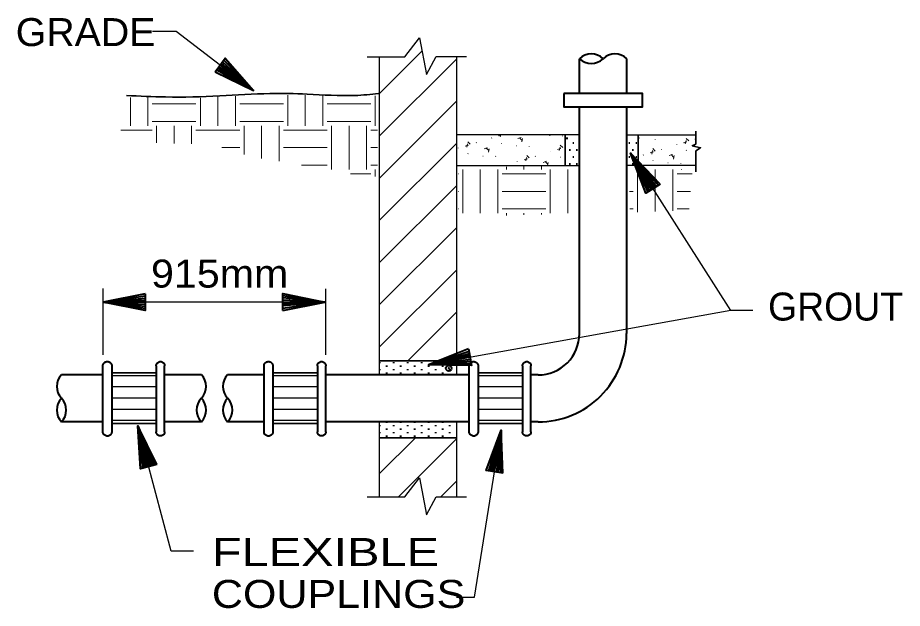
# Model space of a CAD drawing. Extents: x 55 to 190, y 198 to 264.
# Drawn here: x 79.2 to 87.22, y 208.06 to 213.42 of the extents above; entities that cross this region are included whole.
import ezdxf
from ezdxf.enums import TextEntityAlignment as Align

# ---------------------------------------------------------------- set-up
doc = ezdxf.new("R2010")
doc.units = 0
doc.header["$LTSCALE"] = 0.1
doc.header["$PDMODE"] = 32
doc.header["$PDSIZE"] = 0.05
doc.layers.add('2', color=7, linetype='Continuous', lineweight=40)

msp = doc.modelspace()

# ---------------------------------------------------------------- linework, layer by layer
at = {"layer": '2', "lineweight": 13}
for p, q in [((82.4802, 212.7318), (82.8647, 213.1162)), ((82.4805, 212.3487), (83.1772, 213.0456)), ((80.2186, 212.44), (80.2186, 212.6974)), ((80.3773, 212.44), (80.3773, 212.6974)), ((80.8536, 212.44), (80.8536, 212.6932)), ((81.0123, 212.44), (81.0123, 212.7014)), ((81.1711, 212.44), (81.1711, 212.7093)), ((81.6473, 212.44), (81.6473, 212.717)), ((81.8061, 212.44), (81.8061, 212.7175)), ((81.9648, 212.44), (81.9648, 212.7202)), ((82.4411, 212.44), (82.4411, 212.7106)), ((80.417, 212.6384), (80.8139, 212.6384)), ((81.2108, 212.6384), (81.6076, 212.6384)), ((82.0045, 212.6384), (82.4014, 212.6384)), ((82.4805, 211.9656), (83.1772, 212.6625)), ((80.417, 212.4797), (80.8139, 212.4797)), ((80.4567, 212.2844), (80.4567, 212.44)), ((80.6155, 212.2796), (80.6155, 212.44)), ((80.7742, 212.2746), (80.7742, 212.44)), ((81.2108, 212.4797), (81.6076, 212.4797)), ((81.2505, 212.1791), (81.2505, 212.44)), ((81.4092, 212.1418), (81.4092, 212.44)), ((81.568, 212.1201), (81.568, 212.44)), ((82.0045, 212.4797), (82.4014, 212.4797)), ((82.0442, 212.0431), (82.0442, 212.44)), ((82.203, 212.0431), (82.203, 212.44)), ((82.3617, 212.0431), (82.3617, 212.44)), ((80.1305, 212.4003), (80.417, 212.4003)), ((80.8139, 212.4003), (81.2108, 212.4003)), ((81.6076, 212.4003), (82.0045, 212.4003)), ((82.4014, 212.4003), (82.4617, 212.4003)), ((83.56, 212.3484), (83.5904, 212.3577)), ((83.5793, 212.3587), (83.5746, 212.3381)), ((82.4805, 211.5827), (83.1772, 212.2794)), ((83.2777, 212.2762), (83.2706, 212.2455)), ((83.3026, 212.2722), (83.2795, 212.2937)), ((83.3576, 212.2865), (83.3608, 212.2873)), ((83.497, 212.3288), (83.4976, 212.3315)), ((83.5865, 212.2796), (83.5841, 212.2788)), ((83.7637, 212.3339), (83.7333, 212.3246)), ((83.7494, 212.332), (83.7725, 212.3106)), ((83.7711, 212.2928), (83.7783, 212.3238)), ((84.0262, 212.3497), (84.0243, 212.3516)), ((84.1416, 212.3484), (84.141, 212.3458)), ((84.9816, 212.3175), (84.9811, 212.3148)), ((85.2391, 212.2862), (85.2695, 212.2955)), ((85.2618, 212.3071), (85.2547, 212.2762)), ((85.2859, 212.304), (85.2626, 212.3257)), ((85.3404, 212.3172), (85.3433, 212.318)), ((81.0478, 212.2415), (81.2108, 212.2415)), ((81.6076, 212.2415), (82.0045, 212.2415)), ((82.4014, 212.2415), (82.4617, 212.2415)), ((83.1933, 212.2362), (83.1938, 212.2386)), ((83.2565, 212.2555), (83.2867, 212.2648)), ((83.46, 212.241), (83.4296, 212.2317)), ((83.4457, 212.2392), (83.4687, 212.2175)), ((83.4674, 212.2), (83.4745, 212.2309)), ((83.7225, 212.2569), (83.7206, 212.2587)), ((83.8378, 212.2555), (83.8373, 212.2532)), ((84.0333, 212.205), (84.0339, 212.2077)), ((84.0961, 212.2243), (84.1262, 212.2336)), ((84.1177, 212.2452), (84.1106, 212.2143)), ((84.1424, 212.2415), (84.1191, 212.2632)), ((84.9356, 212.1934), (84.9657, 212.2026)), ((84.9578, 212.2143), (84.9507, 212.1833)), ((84.9821, 212.2108), (84.9589, 212.2325)), ((85.0366, 212.2243), (85.0398, 212.2251)), ((85.1771, 212.2669), (85.1777, 212.2693)), ((85.2655, 212.2175), (85.2631, 212.2167)), ((83.283, 212.1868), (83.2803, 212.186)), ((83.4187, 212.1637), (83.4169, 212.1656)), ((83.5341, 212.1629), (83.5335, 212.1603)), ((83.7293, 212.1124), (83.7301, 212.1148)), ((83.7923, 212.1315), (83.8227, 212.141)), ((83.814, 212.1526), (83.8069, 212.1217)), ((83.8386, 212.1487), (83.8153, 212.1701)), ((83.8934, 212.1624), (83.8966, 212.1635)), ((83.996, 212.1172), (83.9656, 212.1079)), ((83.9815, 212.1156), (84.0048, 212.0939)), ((84.1225, 212.1558), (84.1199, 212.155)), ((84.8734, 212.1741), (84.8739, 212.1767)), ((84.962, 212.1249), (84.9594, 212.1241)), ((85.139, 212.1788), (85.1086, 212.1696)), ((85.125, 212.178), (85.1483, 212.1563)), ((85.1475, 212.1381), (85.1546, 212.1688)), ((81.7717, 212.0828), (82.0045, 212.0828)), ((82.4014, 212.0828), (82.4617, 212.0828)), ((82.4411, 211.9783), (82.4411, 212.0431)), ((83.2348, 211.6462), (83.2348, 212.0431)), ((83.3936, 211.6462), (83.3936, 212.0431)), ((83.5523, 211.6462), (83.5523, 212.0431)), ((83.6317, 212.0431), (83.6317, 212.0677)), ((83.7905, 212.0431), (83.7905, 212.069)), ((83.9492, 212.0431), (83.9492, 212.0703)), ((84.004, 212.078), (84.0106, 212.1071)), ((84.0286, 211.6462), (84.0286, 212.0431)), ((84.1873, 211.6462), (84.1873, 212.0431)), ((84.8223, 211.6565), (84.8223, 212.0431)), ((84.9811, 211.6624), (84.9811, 212.0431)), ((85.0983, 212.1026), (85.0964, 212.1045)), ((85.1401, 211.6682), (85.1401, 212.0431)), ((85.2142, 212.1008), (85.2136, 212.0981)), ((85.2192, 212.0431), (85.2192, 212.0457)), ((82.2151, 212.0034), (82.4014, 212.0034)), ((83.193, 212.0034), (83.1951, 212.0034)), ((83.592, 212.0034), (83.9889, 212.0034)), ((85.1795, 212.0034), (85.3158, 212.0034)), ((82.4805, 211.1996), (83.1772, 211.8962)), ((83.193, 211.8447), (83.1951, 211.8447)), ((83.592, 211.8447), (83.9889, 211.8447)), ((84.7488, 211.8447), (84.7826, 211.8447)), ((85.1795, 211.8447), (85.3033, 211.8447)), ((83.193, 211.6859), (83.1951, 211.6859)), ((83.592, 211.6859), (83.9889, 211.6859)), ((83.6317, 211.6269), (83.6317, 211.6462)), ((83.7905, 211.6311), (83.7905, 211.6462)), ((83.9492, 211.6354), (83.9492, 211.6462)), ((84.7527, 211.6859), (84.7826, 211.6859)), ((85.1795, 211.6859), (85.2906, 211.6859)), ((82.4808, 210.8165), (83.1772, 211.5129)), ((82.4808, 210.4334), (83.1774, 211.1298)), ((82.7361, 210.3053), (83.1774, 210.7466)), ((82.4805, 209.2835), (82.8046, 209.6079)), ((82.6538, 209.0737), (83.1772, 209.597)), ((83.0364, 209.0731), (83.1772, 209.2139))]:
    msp.add_line(p, q, dxfattribs=at)
at = {"layer": '2'}
for p, q in [((81.3362, 212.7588), (81.0441, 213.0064)), ((81.3362, 212.7588), (81.0668, 213.0361)), ((84.2937, 212.7323), (84.2937, 213.0485)), ((84.7207, 213.0485), (84.7207, 212.7323)), ((81.3362, 212.7588), (80.9983, 212.9466)), ((81.3362, 212.7588), (81.0107, 212.9638)), ((81.3362, 212.7588), (81.0216, 212.9771)), ((81.0322, 212.9914), (81.3362, 212.7588)), ((84.2937, 210.5532), (84.2937, 212.6112)), ((84.7207, 212.6112), (84.7207, 210.5532)), ((84.1744, 212.3281), (84.1881, 212.3281)), ((84.2339, 212.2844), (84.2445, 212.2844)), ((84.7419, 212.2844), (84.7525, 212.2844)), ((84.8054, 212.2844), (84.816, 212.2844)), ((84.8345, 212.3281), (84.8207, 212.3281)), ((84.2021, 212.2209), (84.2127, 212.2209)), ((84.2656, 212.2209), (84.2762, 212.2209)), ((84.7736, 212.2209), (84.7842, 212.2209)), ((84.2339, 212.1574), (84.2445, 212.1574)), ((84.7419, 212.1574), (84.7525, 212.1574)), ((84.9633, 211.869), (84.7572, 212.1915)), ((84.7572, 212.1915), (84.9927, 211.8875)), ((84.7572, 212.1915), (84.9155, 211.8388)), ((84.7572, 212.1915), (84.947, 211.8589)), ((84.7572, 212.1915), (84.9782, 211.8788)), ((84.7572, 212.1915), (85.0107, 211.8994)), ((84.8054, 212.1574), (84.816, 212.1574)), ((84.2021, 212.0939), (84.2127, 212.0939)), ((84.2656, 212.0939), (84.2762, 212.0939)), ((84.7736, 212.0939), (84.7842, 212.0939)), ((84.8207, 212.0494), (84.8345, 212.0494)), ((79.9699, 210.8395), (80.3522, 210.8964)), ((79.9699, 210.8395), (80.3527, 210.875)), ((79.9699, 210.8395), (80.3522, 210.8578)), ((80.3525, 210.84), (79.9699, 210.8395)), ((79.9699, 210.8395), (80.3522, 210.7834)), ((79.9699, 210.8395), (80.3522, 210.8207)), ((81.9839, 210.8395), (81.601, 210.8041)), ((81.6013, 210.839), (81.9839, 210.8395)), ((81.9839, 210.8395), (81.6016, 210.8956)), ((81.9839, 210.8395), (81.6016, 210.8583)), ((81.9839, 210.8395), (81.6016, 210.8212)), ((81.9839, 210.8395), (81.6016, 210.7826)), ((82.9255, 210.2714), (83.292, 210.395)), ((82.9255, 210.2714), (83.2962, 210.3741)), ((82.9255, 210.2714), (83.2986, 210.3572)), ((82.4832, 210.2841), (82.4832, 210.2947)), ((82.6102, 210.2841), (82.6102, 210.2947)), ((82.7372, 210.2841), (82.7372, 210.2947)), ((82.8642, 210.2841), (82.8642, 210.2947)), ((83.302, 210.3397), (82.9255, 210.2714)), ((82.9255, 210.2714), (83.3052, 210.3207)), ((82.9255, 210.2714), (83.3118, 210.2839)), ((82.9911, 210.2841), (82.9911, 210.2947)), ((83.1182, 210.2841), (83.1182, 210.2947)), ((79.9688, 209.6626), (79.9688, 210.2598)), ((80.0498, 210.2598), (80.0498, 209.6642)), ((80.4535, 210.2617), (80.4535, 209.6626)), ((80.5292, 209.6611), (80.5292, 210.2617)), ((81.4312, 209.6626), (81.4312, 210.2598)), ((81.5119, 210.2598), (81.5119, 209.6642)), ((81.9156, 210.2617), (81.9156, 209.6626)), ((81.9913, 209.6611), (81.9913, 210.2617)), ((82.4832, 210.2206), (82.4832, 210.2312)), ((82.5467, 210.2524), (82.5467, 210.263)), ((82.5467, 210.1889), (82.5467, 210.1995)), ((82.6102, 210.2206), (82.6102, 210.2312)), ((82.6737, 210.2524), (82.6737, 210.263)), ((82.6737, 210.1889), (82.6737, 210.1995)), ((82.7372, 210.2206), (82.7372, 210.2312)), ((82.8007, 210.2524), (82.8007, 210.263)), ((82.8007, 210.1889), (82.8007, 210.1995)), ((82.8642, 210.2206), (82.8642, 210.2312)), ((82.9277, 210.2524), (82.9277, 210.263)), ((82.9277, 210.1889), (82.9277, 210.1995)), ((82.9911, 210.2206), (82.9911, 210.2312)), ((83.0547, 210.2524), (83.0547, 210.263)), ((83.0547, 210.1889), (83.0547, 210.1995)), ((83.1182, 210.2206), (83.1182, 210.2312)), ((83.2933, 209.6626), (83.2933, 210.2598)), ((83.374, 210.2598), (83.374, 209.6642)), ((83.7778, 210.2617), (83.7778, 209.6626)), ((83.8534, 209.6611), (83.8534, 210.2617)), ((79.9688, 210.1788), (79.5934, 210.1788)), ((80.8626, 210.1788), (80.5292, 210.1788)), ((81.4312, 210.1788), (81.1007, 210.1788)), ((83.2938, 210.1788), (81.9913, 210.1788)), ((83.9196, 210.1788), (83.854, 210.1788)), ((79.9688, 209.7521), (79.5934, 209.7521)), ((80.3845, 209.3459), (80.2853, 209.7156)), ((80.2853, 209.7156), (80.4181, 209.3547)), ((80.2853, 209.7156), (80.3297, 209.3316)), ((80.2853, 209.7156), (80.3657, 209.3412)), ((80.2853, 209.7156), (80.4017, 209.3507)), ((80.2853, 209.7156), (80.4387, 209.3607)), ((80.8626, 209.7521), (80.5292, 209.7521)), ((81.4312, 209.7521), (81.1007, 209.7521)), ((83.2938, 209.7521), (81.9913, 209.7521)), ((82.4832, 209.7126), (82.4832, 209.7232)), ((82.5467, 209.7444), (82.5467, 209.7478)), ((82.6102, 209.7126), (82.6102, 209.7232)), ((82.6737, 209.7444), (82.6737, 209.7494)), ((82.7372, 209.7126), (82.7372, 209.7232)), ((82.8007, 209.7444), (82.8007, 209.7507)), ((82.8642, 209.7126), (82.8642, 209.7232)), ((82.9277, 209.7444), (82.9277, 209.7521)), ((82.9911, 209.7126), (82.9911, 209.7232)), ((83.0547, 209.7444), (83.0547, 209.7537)), ((83.1182, 209.7126), (83.1182, 209.7232)), ((83.9196, 209.7521), (83.854, 209.7521)), ((82.4832, 209.6491), (82.4832, 209.6597)), ((82.5467, 209.6809), (82.5467, 209.6915)), ((82.5467, 209.6174), (82.5467, 209.628)), ((82.6102, 209.6491), (82.6102, 209.6597)), ((82.6737, 209.6809), (82.6737, 209.6915)), ((82.6737, 209.6174), (82.6737, 209.628)), ((82.7372, 209.6491), (82.7372, 209.6597)), ((82.8007, 209.6809), (82.8007, 209.6915)), ((82.8007, 209.6174), (82.8007, 209.628)), ((82.8642, 209.6491), (82.8642, 209.6597)), ((82.9277, 209.6809), (82.9277, 209.6915)), ((82.9277, 209.6174), (82.9277, 209.628)), ((82.9911, 209.6491), (82.9911, 209.6597)), ((83.0547, 209.6809), (83.0547, 209.6915)), ((83.0547, 209.6174), (83.0547, 209.628)), ((83.1182, 209.6491), (83.1182, 209.6597)), ((83.5822, 209.6777), (83.4671, 209.3089)), ((83.5822, 209.6777), (83.5039, 209.3031)), ((83.523, 209.2996), (83.5822, 209.6777)), ((83.5822, 209.6777), (83.5407, 209.2972)), ((83.5822, 209.6777), (83.5574, 209.2941)), ((83.5822, 209.6777), (83.5785, 209.2912))]:
    msp.add_line(p, q, dxfattribs=at)
at = {"layer": '2', "lineweight": 25}
for p, q in [((82.4802, 210.1788), (82.4802, 213.0673)), ((83.1772, 213.0673), (83.1772, 210.1788)), ((84.2948, 212.3587), (83.1772, 212.3587)), ((84.7215, 212.3587), (85.3496, 212.3587)), ((83.1772, 212.0799), (84.2948, 212.0799)), ((85.3496, 212.0799), (84.7215, 212.0799)), ((79.9699, 210.3596), (79.9699, 210.9615)), ((81.9908, 210.3622), (81.9908, 210.9588)), ((81.9839, 210.8395), (79.9699, 210.8395)), ((85.6666, 210.7641), (82.9255, 210.2714)), ((80.4535, 210.1691), (80.0498, 210.1691)), ((81.9156, 210.1691), (81.5119, 210.1691)), ((83.7778, 210.1691), (83.374, 210.1691)), ((80.4535, 210.0714), (80.0498, 210.0714)), ((81.9156, 210.0714), (81.5119, 210.0714)), ((83.7778, 210.0714), (83.374, 210.0714)), ((80.4535, 209.9688), (80.0498, 209.9688)), ((81.9156, 209.9688), (81.5119, 209.9688)), ((83.7778, 209.9688), (83.374, 209.9688)), ((80.4535, 209.8645), (80.0498, 209.8645)), ((81.9156, 209.8645), (81.5119, 209.8645)), ((83.7778, 209.8645), (83.374, 209.8645)), ((80.4535, 209.7637), (80.0498, 209.7637)), ((81.9156, 209.7637), (81.5119, 209.7637)), ((82.4802, 209.071), (82.4802, 209.7521)), ((83.1772, 209.7521), (83.1772, 209.071)), ((83.7778, 209.7637), (83.374, 209.7637))]:
    msp.add_line(p, q, dxfattribs=at)
at = {"layer": '2', "lineweight": 35}
for p, q in [((84.163, 212.3587), (84.163, 212.0801)), ((84.826, 212.3587), (84.826, 212.0801)), ((83.1772, 210.3053), (82.4808, 210.3053)), ((80.4535, 210.1976), (80.0498, 210.1976)), ((81.9156, 210.1976), (81.5119, 210.1976)), ((83.7778, 210.1976), (83.374, 210.1976)), ((80.0498, 209.7367), (80.4535, 209.7367)), ((81.5119, 209.7367), (81.9156, 209.7367)), ((83.374, 209.7367), (83.7778, 209.7367)), ((83.1772, 209.6079), (82.48, 209.6079))]:
    msp.add_line(p, q, dxfattribs=at)
at = {"layer": '2', "lineweight": 25}
for points in [[(80.4205, 213.298), (80.6337, 213.298), (81.3362, 212.7588)], [(82.3675, 213.0668), (82.7099, 213.0668), (82.8414, 213.2387), (82.9052, 212.9043), (82.9943, 213.0686), (83.269, 213.0686)], [(85.8688, 210.7641), (85.6666, 210.7641), (84.7572, 212.1915)], [(80.7906, 208.5786), (80.5885, 208.5786), (80.2853, 209.7156)], [(83.1782, 208.1617), (83.3422, 208.1617), (83.5822, 209.6777)], [(82.3675, 209.0713), (82.7099, 209.0713), (82.8414, 209.2433), (82.9052, 208.9088), (82.9943, 209.0731), (83.269, 209.0731)]]:
    msp.add_lwpolyline(points, dxfattribs=at)
at = {"layer": '2'}
for points in [[(80.9864, 212.931), (81.0798, 213.0525), (81.3362, 212.7588)], [(80.9864, 212.931), (81.3362, 212.7588), (81.0554, 213.0215)], [(85.0271, 211.91), (84.8977, 211.828), (84.7572, 212.1915)], [(85.0271, 211.91), (84.7572, 212.1915), (84.9311, 211.8486)], [(80.3522, 210.9157), (80.3519, 210.7628), (79.9699, 210.8395)], [(80.3522, 210.9157), (79.9699, 210.8395), (80.3525, 210.8019)], [(81.6016, 210.7633), (81.6018, 210.9162), (81.9839, 210.8395)], [(81.6016, 210.7633), (81.9839, 210.8395), (81.6013, 210.8771)], [(83.2885, 210.4141), (83.3153, 210.2635), (82.9255, 210.2714)], [(83.2885, 210.4141), (82.9255, 210.2714), (83.3089, 210.3021)], [(79.9688, 210.2598), (79.9693, 210.2662), (79.9709, 210.2722), (79.9733, 210.2783), (79.9767, 210.2836), (79.9807, 210.2884), (79.9855, 210.2926), (79.991, 210.2958), (79.9969, 210.2982), (80.0029, 210.2998), (80.0093, 210.3003), (80.0156, 210.2998), (80.0217, 210.2982), (80.0276, 210.2958), (80.0331, 210.2926), (80.0379, 210.2884), (80.0418, 210.2836), (80.0453, 210.2783), (80.0477, 210.2722), (80.0492, 210.2662), (80.0498, 210.2598)], [(80.4535, 210.2617), (80.4538, 210.2675), (80.4554, 210.2733), (80.4575, 210.2789), (80.4607, 210.2839), (80.4646, 210.2884), (80.4691, 210.2921), (80.4742, 210.2953), (80.4795, 210.2976), (80.4853, 210.299), (80.4914, 210.2995), (80.4972, 210.299), (80.503, 210.2976), (80.5086, 210.2953), (80.5136, 210.2921), (80.5181, 210.2884), (80.5218, 210.2839), (80.525, 210.2789), (80.5274, 210.2733), (80.5287, 210.2675), (80.5292, 210.2617)], [(81.4312, 210.2598), (81.4314, 210.2662), (81.433, 210.2722), (81.4354, 210.2783), (81.4388, 210.2836), (81.4428, 210.2884), (81.4476, 210.2926), (81.4531, 210.2958), (81.4589, 210.2982), (81.465, 210.2998), (81.4714, 210.3003), (81.4777, 210.2998), (81.4838, 210.2982), (81.4896, 210.2958), (81.4952, 210.2926), (81.5, 210.2884), (81.5042, 210.2836), (81.5074, 210.2783), (81.5097, 210.2722), (81.5113, 210.2662), (81.5119, 210.2598)], [(81.9156, 210.2617), (81.9159, 210.2675), (81.9175, 210.2733), (81.9196, 210.2789), (81.9228, 210.2839), (81.9267, 210.2884), (81.9312, 210.2921), (81.9363, 210.2953), (81.9418, 210.2976), (81.9474, 210.299), (81.9535, 210.2995), (81.9593, 210.299), (81.9651, 210.2976), (81.9707, 210.2953), (81.9757, 210.2921), (81.9802, 210.2884), (81.9841, 210.2839), (81.987, 210.2789), (81.9894, 210.2733), (81.9908, 210.2675), (81.9913, 210.2617)], [(83.2933, 210.2598), (83.2938, 210.2662), (83.2951, 210.2722), (83.2975, 210.2783), (83.301, 210.2836), (83.3049, 210.2884), (83.31, 210.2926), (83.3153, 210.2958), (83.3211, 210.2982), (83.3272, 210.2998), (83.3335, 210.3003), (83.3399, 210.2998), (83.346, 210.2982), (83.3518, 210.2958), (83.3573, 210.2926), (83.3621, 210.2884), (83.3663, 210.2836), (83.3695, 210.2783), (83.3719, 210.2722), (83.3735, 210.2662), (83.374, 210.2598)], [(83.7778, 210.2617), (83.7783, 210.2675), (83.7796, 210.2733), (83.7817, 210.2789), (83.7849, 210.2839), (83.7889, 210.2884), (83.7934, 210.2921), (83.7984, 210.2953), (83.804, 210.2976), (83.8098, 210.299), (83.8156, 210.2995), (83.8214, 210.299), (83.8272, 210.2976), (83.8328, 210.2953), (83.8378, 210.2921), (83.8423, 210.2884), (83.8463, 210.2839), (83.8492, 210.2789), (83.8516, 210.2733), (83.8529, 210.2675), (83.8534, 210.2617)], [(80.4575, 209.3658), (80.3096, 209.3266), (80.2853, 209.7156)], [(80.4575, 209.3658), (80.2853, 209.7156), (80.3474, 209.3361)], [(80.0498, 209.6642), (80.0492, 209.6581), (80.0479, 209.6518), (80.0455, 209.646), (80.0424, 209.6404), (80.0384, 209.6357), (80.0336, 209.6314), (80.0283, 209.628), (80.0225, 209.6253), (80.0164, 209.6237), (80.0101, 209.6232), (80.0037, 209.6235), (79.9977, 209.6248), (79.9918, 209.6272), (79.9863, 209.6304), (79.9813, 209.6343), (79.977, 209.6391), (79.9736, 209.6444), (79.9712, 209.6502), (79.9696, 209.6563), (79.9688, 209.6626)], [(80.5292, 209.6611), (80.5284, 209.655), (80.5271, 209.6494), (80.5247, 209.6439), (80.5215, 209.6388), (80.5176, 209.6343), (80.5128, 209.6306), (80.5078, 209.6277), (80.5022, 209.6256), (80.4964, 209.6243), (80.4903, 209.624), (80.4845, 209.6245), (80.4787, 209.6261), (80.4734, 209.6285), (80.4683, 209.6317), (80.4639, 209.6357), (80.4601, 209.6401), (80.4572, 209.6454), (80.4551, 209.651), (80.4538, 209.6568), (80.4535, 209.6626)], [(81.5119, 209.6642), (81.5113, 209.6581), (81.51, 209.6518), (81.5079, 209.646), (81.5045, 209.6404), (81.5005, 209.6357), (81.4957, 209.6314), (81.4904, 209.628), (81.4846, 209.6253), (81.4785, 209.6237), (81.4722, 209.6232), (81.4658, 209.6235), (81.4597, 209.6248), (81.4539, 209.6272), (81.4484, 209.6304), (81.4433, 209.6343), (81.4394, 209.6391), (81.4359, 209.6444), (81.4333, 209.6502), (81.4317, 209.6563), (81.4312, 209.6626)], [(81.9913, 209.6611), (81.9908, 209.655), (81.9892, 209.6494), (81.9868, 209.6439), (81.9836, 209.6388), (81.9796, 209.6343), (81.9749, 209.6306), (81.9699, 209.6277), (81.9643, 209.6256), (81.9585, 209.6243), (81.9527, 209.624), (81.9466, 209.6245), (81.941, 209.6261), (81.9355, 209.6285), (81.9304, 209.6317), (81.9259, 209.6357), (81.9222, 209.6401), (81.9193, 209.6454), (81.9172, 209.651), (81.9159, 209.6568), (81.9156, 209.6626)], [(83.374, 209.6642), (83.3735, 209.6581), (83.3722, 209.6518), (83.37, 209.646), (83.3669, 209.6404), (83.3626, 209.6357), (83.3579, 209.6314), (83.3526, 209.628), (83.3468, 209.6253), (83.3407, 209.6237), (83.3343, 209.6232), (83.328, 209.6235), (83.3219, 209.6248), (83.3161, 209.6272), (83.3105, 209.6304), (83.3057, 209.6343), (83.3015, 209.6391), (83.2981, 209.6444), (83.2954, 209.6502), (83.2938, 209.6563), (83.2933, 209.6626)], [(83.5978, 209.288), (83.4465, 209.3123), (83.5822, 209.6777)], [(83.5978, 209.288), (83.5822, 209.6777), (83.4854, 209.3057)], [(83.8534, 209.6611), (83.8529, 209.655), (83.8513, 209.6494), (83.8489, 209.6439), (83.8458, 209.6388), (83.8418, 209.6343), (83.837, 209.6306), (83.832, 209.6277), (83.8264, 209.6256), (83.8206, 209.6243), (83.8148, 209.624), (83.8087, 209.6245), (83.8031, 209.6261), (83.7976, 209.6285), (83.7926, 209.6317), (83.7881, 209.6357), (83.7844, 209.6401), (83.7815, 209.6454), (83.7793, 209.651), (83.778, 209.6568), (83.7778, 209.6626)]]:
    msp.add_lwpolyline(points, dxfattribs=at)
msp.add_lwpolyline([(84.1521, 212.7323), (84.1521, 212.6112), (84.8655, 212.6112), (84.8655, 212.7323)], close=True, dxfattribs=at)
at = {"layer": '2', "lineweight": 35}
msp.add_lwpolyline([(85.3502, 212.391), (85.3502, 212.2738), (85.3171, 212.2585), (85.3936, 212.2405), (85.3502, 212.2124), (85.3502, 212.0211)], dxfattribs=at)
at = {"layer": '2'}
for centre, radius, start, end in [((84.4009, 212.9376), 0.1543, 45.9775, 134.02119), ((84.6154, 212.9376), 0.1543, 45.97881, 134.0225), ((84.4009, 213.1595), 0.1543, 225.97881, 314.0225), ((83.9196, 210.5531), 0.801, 269.98171, 0), ((83.9196, 210.5531), 0.3742, 269.98271, 360), ((79.7043, 210.0735), 0.1543, 135.97881, 224.0225), ((80.7516, 210.0735), 0.1543, 315.9775, 44.02119), ((81.2116, 210.0735), 0.1543, 135.97881, 224.0225), ((79.7043, 209.859), 0.1543, 135.9775, 224.02119), ((79.4824, 209.859), 0.1543, 315.97881, 44.0225), ((80.9735, 209.859), 0.1543, 135.9775, 224.02119), ((80.7516, 209.859), 0.1543, 315.97881, 44.0225), ((81.2116, 209.859), 0.1543, 135.9775, 224.02119), ((80.9898, 209.859), 0.1543, 315.97881, 44.0225)]:
    msp.add_arc(centre, radius, start, end, dxfattribs=at)
at = {"layer": '2', "lineweight": 35}
msp.add_spline([(82.4712, 212.7323), (82.2567, 212.7149), (81.8228, 212.7278), (81.4851, 212.7323), (81.0293, 212.7104), (80.5385, 212.7016), (80.1834, 212.7149)], degree=3, dxfattribs=at)
at = {"layer": '2'}
msp.add_point((83.1076, 210.2384), dxfattribs=at)

# ---------------------------------------------------------------- texts
for s, width, p in [('GRADE', 1.05, (79.1777, 213.1633)), ('FLEXIBLE', 1.3, (80.9578, 208.4445)), ('COUPLINGS', 1.15, (80.9578, 208.0635))]:
    msp.add_text(s, height=0.254, dxfattribs=dict(at, width=width)).set_placement(p)
at = {"layer": '2', "width": 1.1}
msp.add_text('915mm', height=0.254, dxfattribs=at).set_placement((81.0286, 210.9711), align=Align.CENTER)
at = {"layer": '2'}
msp.add_text('GROUT', height=0.254, dxfattribs=at).set_placement((86.0055, 210.672))

doc.saveas('drawing.dxf')
